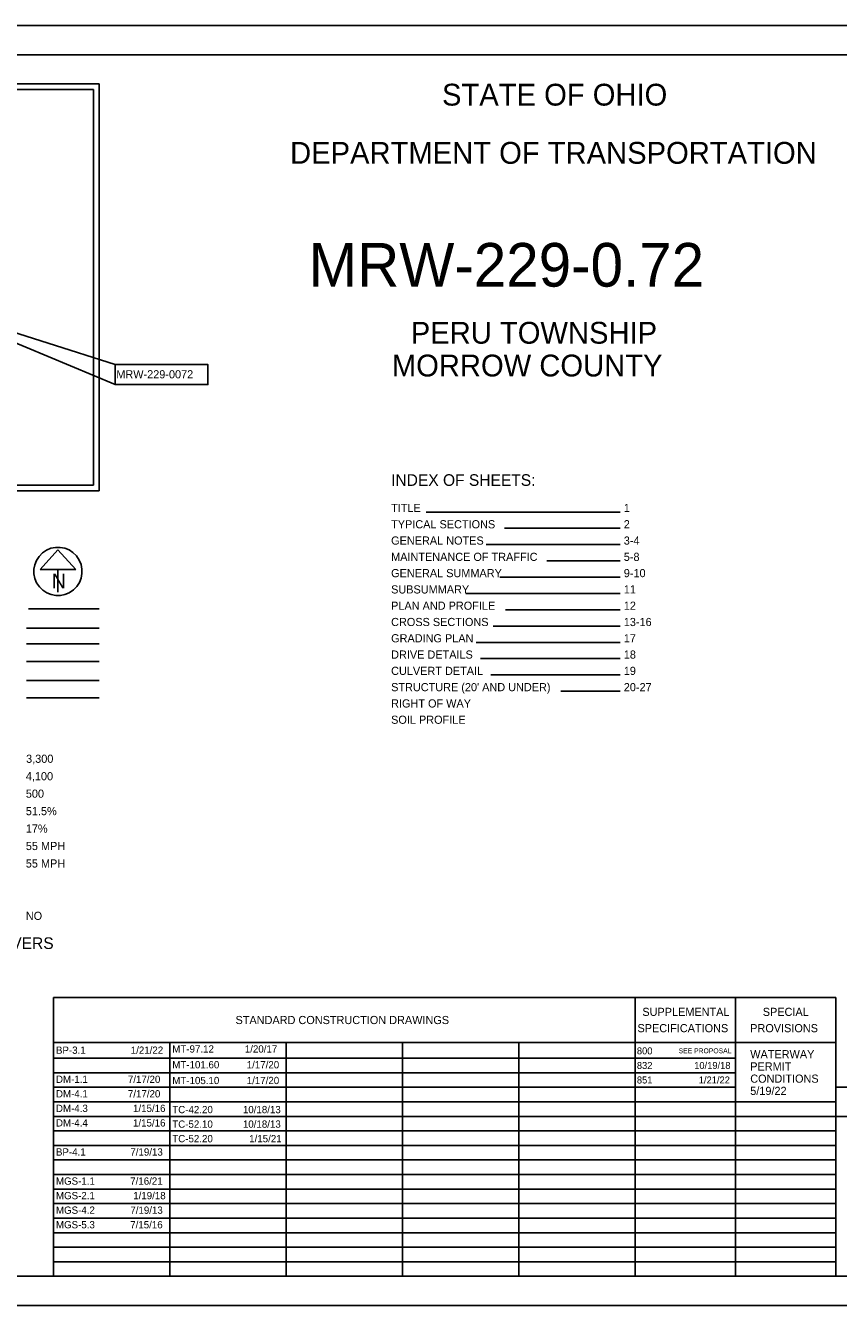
# Model space of a CAD drawing. Extents: x 0 to 34, y 0 to 22.
# Drawn here: x 8.23 to 22.21, y 0 to 22 of the extents above; entities that cross this region are included whole.
import ezdxf

# ---------------------------------------------------------------- set-up
doc = ezdxf.new("R2010")
doc.units = 0
for name, color, linetype in [('BR_P_Beam_Text', 7, 'Continuous'), ('SH_Border', 7, 'Continuous'), ('SH_Cut_Line', 7, 'Continuous'), ('SH_Data', 7, 'Continuous')]:
    doc.layers.add(name, color=color, linetype=linetype)

msp = doc.modelspace()

# ---------------------------------------------------------------- linework, layer by layer
at = {"layer": 'SH_Border'}
msp.add_lwpolyline([(2, 21.5), (33.5, 21.5), (33.5, 0.5), (2, 0.5)], close=True, dxfattribs=at)
at = {"layer": 'SH_Cut_Line'}
msp.add_lwpolyline([(0, 0), (34, 0), (34, 22), (0, 22)], close=True, dxfattribs=at)
at = {"layer": 'SH_Data'}
for p, q in [((2.5, 21), (9.5, 21)), ((2.5, 21), (9.5, 21)), ((2.6, 20.9), (9.4, 20.9)), ((2.6, 20.9), (9.4, 20.9)), ((9.4, 20.9), (9.4, 14.1)), ((9.4, 20.9), (9.4, 14.1)), ((9.5, 21), (9.5, 14)), ((9.5, 21), (9.5, 14)), ((2.6, 14.1), (9.4, 14.1)), ((2.6, 14.1), (9.4, 14.1)), ((2.5, 14), (9.5, 14)), ((2.5, 14), (9.5, 14)), ((18.455, 13.638), (15.121, 13.638)), ((18.455, 13.358), (16.464, 13.358)), ((8.789, 12.991), (8.482, 12.65)), ((9.097, 12.65), (8.789, 12.991)), ((18.455, 13.078), (16.152, 13.078)), ((18.455, 12.798), (17.192, 12.798)), ((8.482, 12.65), (9.097, 12.65)), ((8.789, 12.65), (8.789, 12.263)), ((8.789, 12.617), (8.789, 12.617)), ((8.789, 12.617), (8.789, 12.617)), ((8.789, 12.617), (8.789, 12.617)), ((8.789, 12.617), (8.789, 12.617)), ((18.455, 12.518), (16.388, 12.518)), ((18.455, 12.238), (15.804, 12.238)), ((8.283, 11.976), (9.5, 11.976)), ((18.455, 11.958), (16.481, 11.958)), ((18.455, 11.678), (16.269, 11.678)), ((9.5, 11.642), (8.25, 11.642)), ((9.5, 11.37), (8.25, 11.37)), ((18.455, 11.398), (15.977, 11.398)), ((9.5, 11.07), (8.25, 11.07)), ((18.455, 11.118), (16.051, 11.118)), ((18.455, 10.838), (16.231, 10.838)), ((9.5, 10.743), (8.25, 10.743)), ((9.5, 10.443), (8.25, 10.443)), ((18.455, 10.558), (17.436, 10.558)), ((8.712, 5.292), (22.162, 5.292)), ((8.712, 0.5), (8.712, 5.292)), ((8.712, 5.292), (22.162, 5.292)), ((8.712, 0.5), (8.712, 5.292)), ((18.712, 0.5), (18.712, 5.292)), ((18.712, 0.5), (18.712, 5.292)), ((20.437, 0.5), (20.437, 5.292)), ((20.437, 0.5), (20.437, 5.292)), ((22.162, 0.5), (22.162, 5.292)), ((22.162, 0.5), (22.162, 5.292)), ((8.712, 4.521), (22.162, 4.521)), ((8.712, 4.521), (22.162, 4.521)), ((10.712, 0.5), (10.712, 4.521)), ((10.712, 0.5), (10.712, 4.521)), ((12.712, 0.5), (12.712, 4.521)), ((12.712, 0.5), (12.712, 4.521)), ((14.712, 0.5), (14.712, 4.521)), ((14.712, 0.5), (14.712, 4.521)), ((16.712, 0.5), (16.712, 4.521)), ((16.712, 0.5), (16.712, 4.521)), ((8.712, 4.25), (20.437, 4.25)), ((8.712, 4.25), (20.437, 4.25)), ((8.712, 4), (20.437, 4)), ((8.712, 4), (20.437, 4)), ((8.712, 3.75), (20.437, 3.75)), ((8.712, 3.75), (20.437, 3.75)), ((22.162, 0.5), (22.162, 3.75)), ((22.162, 3.75), (24.962, 3.75)), ((8.712, 3.5), (22.162, 3.5)), ((8.712, 3.5), (22.162, 3.5)), ((8.712, 3.25), (22.162, 3.25)), ((8.712, 3.25), (22.162, 3.25)), ((22.162, 3.25), (24.962, 3.25)), ((8.712, 3), (22.162, 3)), ((8.712, 3), (22.162, 3)), ((8.712, 2.75), (22.162, 2.75)), ((8.712, 2.75), (22.162, 2.75)), ((8.712, 2.5), (22.162, 2.5)), ((8.712, 2.5), (22.162, 2.5)), ((8.712, 2.25), (22.162, 2.25)), ((8.712, 2.25), (22.162, 2.25)), ((8.712, 2), (22.162, 2)), ((8.712, 2), (22.162, 2)), ((8.712, 1.75), (22.162, 1.75)), ((8.712, 1.75), (22.162, 1.75)), ((8.712, 1.5), (22.162, 1.5)), ((8.712, 1.5), (22.162, 1.5)), ((8.712, 1.25), (22.162, 1.25)), ((8.712, 1.25), (22.162, 1.25)), ((8.712, 1), (22.162, 1)), ((8.712, 1), (22.162, 1)), ((8.712, 0.75), (22.162, 0.75)), ((8.712, 0.75), (22.162, 0.75))]:
    msp.add_line(p, q, dxfattribs=at)
for points in [[(6.309, 17.272), (9.771, 15.83), (9.771, 16.174)], [(9.771, 16.174), (11.368, 16.174), (11.368, 15.83), (9.771, 15.83)]]:
    msp.add_lwpolyline(points, close=True, dxfattribs=at)
msp.add_arc((8.789, 12.617), 0.415, 129.7798, 129.7633, dxfattribs=at)

# ---------------------------------------------------------------- texts
at = {"layer": 'BR_P_Beam_Text'}
msp.add_text('MRW-229-0072', height=0.14, dxfattribs=at).set_placement((9.793, 15.936))
at = {"layer": 'SH_Data'}
for s, height, p in [('STATE OF OHIO', 0.375, (15.392, 20.625)), ('DEPARTMENT OF TRANSPORTATION', 0.375, (12.78, 19.625)), ('MRW-229-0.72', 0.75, (13.098, 17.513)), ('PERU TOWNSHIP', 0.375, (14.855, 16.532)), ('MORROW COUNTY ', 0.375, (14.53, 15.969)), ('INDEX OF SHEETS:', 0.2, (14.517, 14.088)), ('TITLE', 0.14, (14.517, 13.638)), ('1', 0.14, (18.517, 13.638)), ('TYPICAL SECTIONS ', 0.14, (14.517, 13.358)), ('2', 0.14, (18.517, 13.358)), ('GENERAL NOTES', 0.14, (14.517, 13.078)), ('3-4', 0.14, (18.517, 13.078)), ('MAINTENANCE OF TRAFFIC', 0.14, (14.517, 12.798)), ('5-8', 0.14, (18.517, 12.798)), ('GENERAL SUMMARY', 0.14, (14.517, 12.518)), ('9-10', 0.14, (18.517, 12.518)), ('SUBSUMMARY', 0.14, (14.517, 12.238)), ('11', 0.14, (18.517, 12.238)), ('PLAN AND PROFILE', 0.14, (14.517, 11.958)), ('12', 0.14, (18.517, 11.958)), ('CROSS SECTIONS', 0.14, (14.517, 11.678)), ('13-16', 0.14, (18.517, 11.678)), ('GRADING PLAN', 0.14, (14.517, 11.398)), ('17', 0.14, (18.517, 11.398)), ('DRIVE DETAILS', 0.14, (14.517, 11.118)), ('18', 0.14, (18.517, 11.118)), ('CULVERT DETAIL', 0.14, (14.517, 10.838)), ('19', 0.14, (18.517, 10.838)), ("STRUCTURE (20' AND UNDER)", 0.14, (14.517, 10.558)), ('20-27', 0.14, (18.517, 10.558)), ('RIGHT OF WAY', 0.14, (14.517, 10.278)), ('SOIL PROFILE', 0.14, (14.517, 9.998)), ('3,300', 0.14, (8.242, 9.327)), ('4,100', 0.14, (8.237, 9.027)), ('500', 0.14, (8.237, 8.727)), ('51.5%', 0.14, (8.237, 8.427)), ('17%', 0.14, (8.237, 8.127)), ('55 MPH', 0.14, (8.237, 7.827)), ('55 MPH', 0.14, (8.237, 7.527)), ('NO', 0.14, (8.237, 6.627)), ('ADA DESIGN WAIVERS', 0.2, (5.758, 6.127)), ('SUPPLEMENTAL', 0.14, (18.836, 4.976)), ('SPECIAL', 0.14, (20.906, 4.976)), ('STANDARD CONSTRUCTION DRAWINGS', 0.14, (11.842, 4.836)), ('SPECIFICATIONS', 0.14, (18.752, 4.696)), ('PROVISIONS', 0.14, (20.69, 4.696)), ('BP-3.1', 0.125, (8.755, 4.325)), ('1/21/22', 0.125, (10.041, 4.325)), ('MT-97.12', 0.125, (10.755, 4.346)), ('1/20/17', 0.125, (12.002, 4.346)), ('800', 0.12, (18.742, 4.315)), ('SEE PROPOSAL', 0.08449, (19.46, 4.334)), ('MT-101.60', 0.125, (10.755, 4.075)), ('1/17/20', 0.125, (12.035, 4.075)), ('832', 0.12, (18.742, 4.065)), ('10/19/18', 0.12, (19.727, 4.065)), ('WATERWAY ', 0.14, (20.691, 4.248)), ('CONDITIONS', 0.14, (20.691, 3.828)), ('PERMIT ', 0.14, (20.691, 4.038)), ('DM-1.1', 0.125, (8.755, 3.825)), ('7/17/20', 0.125, (9.992, 3.825)), ('MT-105.10', 0.125, (10.755, 3.804)), ('1/17/20', 0.125, (12.035, 3.804)), ('851', 0.12, (18.742, 3.815)), ('1/21/22', 0.12, (19.806, 3.815)), ('5/19/22', 0.14, (20.691, 3.618)), ('DM-4.1', 0.125, (8.755, 3.575)), ('7/17/20', 0.125, (9.992, 3.575)), ('DM-4.3', 0.125, (8.755, 3.325)), ('1/15/16', 0.125, (10.08, 3.325)), ('TC-42.20', 0.125, (10.755, 3.304)), ('10/18/13', 0.125, (11.969, 3.304)), ('DM-4.4', 0.125, (8.755, 3.075)), ('1/15/16', 0.125, (10.08, 3.075)), ('TC-52.10', 0.125, (10.755, 3.054)), ('10/18/13', 0.125, (11.969, 3.054)), ('TC-52.20', 0.125, (10.755, 2.804)), ('1/15/21', 0.125, (12.077, 2.804)), ('BP-4.1', 0.125, (8.755, 2.575)), ('7/19/13', 0.125, (10.034, 2.575)), ('MGS-1.1', 0.125, (8.755, 2.075)), ('7/16/21', 0.125, (10.032, 2.075)), ('MGS-2.1', 0.125, (8.755, 1.825)), ('1/19/18', 0.125, (10.083, 1.825)), ('MGS-4.2', 0.125, (8.755, 1.575)), ('7/19/13', 0.125, (10.034, 1.575)), ('MGS-5.3', 0.125, (8.755, 1.325)), ('7/15/16', 0.125, (10.032, 1.325))]:
    msp.add_text(s, height=height, dxfattribs=at).set_placement(p)
msp.add_text('N', height=0.25, rotation=360, dxfattribs=at).set_placement((8.685, 12.326))

doc.saveas('drawing.dxf')
